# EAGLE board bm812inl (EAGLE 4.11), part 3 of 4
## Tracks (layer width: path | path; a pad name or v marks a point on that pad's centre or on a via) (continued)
N$1 (continued)
  Top 0.254: B15.B1 80.68,202.55 80.68,197.47 B15.D1 80.68,196.2 79.73,195.25 79.73,185.73 80.68,184.77 B15.J1 | B15.H1 83.86,186.68 83.86,181.6 B15.K1 83.86,180.33 82.9,179.37 82.9,171.76 | B15.V1 80.68,153.02 79.73,153.98 79.73,163.5 80.68,164.45 B15.R1 80.68,165.72 80.68,170.8 B15.N1 81.63,171.76 82.9,171.76 | 82.9,171.76 83.54,171.12 83.54,169.21 83.86,168.9 B15.P1
  Bottom 0.254: B15.C1 83.54,200.33 81.32,202.55 B15.B1 | B15.J1 81.63,184.46 85.13,184.46 85.76,185.09 85.76,186.68 84.49,186.68 B15.H1
N$2
  Top 0.254: B15.U2 77.51,156.2 77.51,161.28 B15.S2 | 76.55,188.27 77.19,187.63 B15.H2 | 76.55,188.27 74.97,189.85 B15.F2 75.28,190.8 77.51,193.03 B15.E2 | 76.55,188.27 76.55,180.01 74.97,178.42 B15.L2 74.97,177.15 77.19,174.93 B15.M2 77.19,174.3 74.97,172.07 B15.N2 74.65,166.99 73.38,165.72 73.38,160.33 74.33,159.37 B15.T2
  Bottom 0.254: B15.U2 78.46,155.24 83.54,155.24 B15.U1 | B15.T2 75.28,159.05 77.51,161.28 B15.S2
N$4
  Top 0.254: C15.B1 81.32,139.05 83.54,136.83 C15.C1 83.86,135.88 81.63,133.65 C15.D1 81.32,132.7 82.9,131.11 82.9,122.22 | 82.9,122.22 81.63,120.96 C15.J1 81.32,120 83.54,117.78 C15.K1 83.86,116.83 82.9,115.88 82.9,108.57 | 82.9,122.22 83.86,123.18 C15.H1 | C15.V1 80.68,89.52 79.73,90.47 79.73,100 80.68,100.95 C15.R1 80.68,102.22 80.68,107.3 C15.N1 81.32,108.57 82.9,108.57 | 82.9,108.57 83.54,107.94 83.54,105.72 83.86,105.4 C15.P1
N$6
  Top 0.254: C15.U2 77.19,92.38 74.97,94.6 C15.T2 75.28,95.55 77.51,97.78 C15.S2 77.51,99.05 75.92,100.63 75.92,108.89 | 75.92,108.89 77.51,110.48 C15.M2 77.19,111.43 74.97,113.65 C15.L2 74.97,114.92 75.92,115.88 75.92,123.81 | 75.92,108.89 75.28,108.25 C15.N2 | 75.92,123.81 74.97,123.81 74.97,126.35 C15.F2 | 75.92,123.81 C15.H2 77.51,124.45 77.51,129.53 C15.E2
  Bottom 0.254: C15.U1 83.54,91.74 78.46,91.74 C15.U2
N$8  (via drill 0.61)
  Top 0.254: 73.38,60.31 73.38,61.9 74.33,62.85 D15.D2 75.28,63.81 79.09,63.81 79.09,72.06 | 73.38,60.31 73.38,46.03 74.33,45.07 D15.L2 | 73.38,60.31 79.09,54.6 79.09,54.28 83.54,54.28 D15.H1 | v79.09,182.23 79.09,72.06 | 79.09,72.06 80.68,70.47 D15.B1
  Bottom 0.254: v79.09,182.23 60.36,182.23 59.41,181.28 B17.K1
N$10
  Bottom 0.254: 107.99,277.48 98.46,277.48 97.51,276.53 A14.A1 | 107.99,277.48 108.94,276.53 A13.A1 | 120.69,277.48 121.64,276.53 A12.A1 | 120.69,277.48 107.99,277.48 | 133.39,277.48 134.34,276.53 A11.A1 | 133.39,277.48 120.69,277.48 | 146.09,277.48 147.04,276.53 A10.A1 | 146.09,277.48 133.39,277.48 | 158.79,277.48 159.74,276.53 A09.A1 | 158.79,277.48 146.09,277.48 | 158.79,277.48 171.49,277.48 172.44,276.53 A08.A1 173.71,275.9 174.66,274.94 184.19,274.94 | 184.19,274.94 185.14,275.9 A07.A1 | 196.89,274.94 197.84,275.9 A06.A1 | 196.89,274.94 184.19,274.94 | 209.59,274.94 210.54,275.9 A05.A1 | 209.59,274.94 196.89,274.94 | 222.29,274.94 223.24,275.9 A04.A1 | 222.29,274.94 209.59,274.94 | 234.99,274.94 235.94,275.9 A03.A1 | 234.99,274.94 222.29,274.94 | 247.69,274.94 248.64,275.9 A02.A1 | 234.99,274.94 247.69,274.94 | 247.69,274.94 260.39,274.94 261.34,275.9 A01.A1
N$12  (via drill 0.61)
  Top 0.254: v17.82,186.68 16.23,185.09 v16.23,181.28 | v25.44,169.85 v25.44,178.11 | v12.1,169.53 9.24,166.68 9.24,153.34 8.61,152.71 8.61,150.8 v8.93,150.48 | v72.11,33.01 74.33,33.01 74.33,32.37 D15.R2
  Bottom 0.254: v17.82,186.68 19.72,186.68 20.04,186.99 B20.H1 | v16.23,181.28 17.18,180.33 19.4,180.33 20.67,179.06 24.48,179.06 v25.44,178.11 | v25.44,169.85 25.12,169.53 22.26,169.53 21.63,170.17 12.74,170.17 v12.1,169.53 | v8.93,150.48 8.93,149.85 3.21,144.13 3.21,55.23 16.23,55.23 38.45,33.01 v72.11,33.01
N$14  (via drill 0.61)
  Top 0.254: v29.88,207.31 30.83,208.27 30.83,220.97 31.47,221.6 31.47,223.51 v30.52,224.46 | v112.11,227 111.48,226.36 111.48,200.33 114.02,197.79 114.02,193.03 115.29,191.76 115.29,189.85 114.65,189.22 114.65,150.48 v114.97,150.17 | v87.67,147.31 86.08,145.72 86.08,88.25 86.4,87.94 86.4,70.79 86.08,70.47 86.08,60.95 v86.4,60.63
  Bottom 0.254: v29.88,207.31 27.66,205.09 22.26,205.09 21.31,206.05 B20.A1 | v30.52,224.46 33.37,227.32 111.8,227.32 v112.11,227 | v114.97,150.17 112.11,147.31 v87.67,147.31 | v86.4,60.63 83.22,57.46 81.63,57.46 D15.F1
N$15  (via drill 0.61)
  Top 0.254: v84.49,39.04 82.9,40.63 82.9,41.58 81.95,41.58 76.55,46.98 76.55,48.57 74.97,50.15 D15.J2 | v128.31,39.04 162.28,73.01 162.28,258.43 137.83,282.88 2.58,282.88 v2.58,237.8
  Bottom 0.254: v84.49,39.04 84.81,39.36 127.99,39.36 v128.31,39.04 | v2.58,237.8 2.58,204.46 13.69,204.46 14.64,203.51 16.86,203.51 B20.B1
N$16  (via drill 0.61)
  Top 0.254: D15.S2 78.14,29.2 79.73,30.78 79.73,36.5 80.68,37.45 D15.N1 80.36,38.4 75.92,38.4 75.92,41.26 72.74,44.44 72.74,76.19 | D16.D2 62.58,63.81 65.76,63.81 65.76,65.39 67.98,67.61 67.98,69.2 D16.B1 68.62,70.47 68.62,72.06 72.74,76.19 | v52.74,147.31 50.84,149.21 50.84,174.93 51.79,175.88 51.79,180.01 52.11,180.33 B17.K2 | v71.16,146.04 72.74,144.45 72.74,82.22 73.06,81.9 73.06,76.5 72.74,76.19
  Bottom 0.254: v52.74,147.31 54.01,146.04 v71.16,146.04
N$17  (via drill 0.61)
  Top 0.254: v74.33,53.01 82.27,45.07 82.27,43.49 83.86,41.9 D15.M1 | v25.75,71.74 v25.75,115.24 | v25.75,122.54 25.75,152.39 v27.02,153.66 | v22.9,155.88 22.58,156.2 22.58,161.28 23.21,161.91 23.21,163.82 22.58,164.45 22.58,186.68 v22.9,186.99
  Bottom 0.254: v74.33,53.01 74.01,52.69 46.71,52.69 43.53,49.52 29.56,49.52 25.75,53.33 v25.75,71.74 | v25.75,115.24 v25.75,122.54 | v27.02,153.66 24.8,155.88 v22.9,155.88 | v22.9,186.99 19.72,190.17 18.13,190.17 B20.F1
N$20  (via drill 0.61)
  Top 0.254: 28.93,179.06 28.93,182.55 29.88,183.5 B19.J1 30.52,184.77 30.52,187.63 v32.42,189.54 32.1,189.85 32.1,198.43 33.06,199.38 B19.C1 | 28.93,179.06 28.93,176.83 27.34,175.25 B19.M2 | v20.99,164.14 19.4,162.55 19.4,154.29 22.58,154.29 23.85,155.56 B19.T2 | v37.5,122.54 37.82,122.86 37.82,160.33 33.69,164.45 33.69,167.63 B19.P1 33.06,168.9 32.1,169.85 32.1,179.06 28.93,179.06
  Bottom 0.254: v32.42,189.54 32.1,189.22 25.44,189.22 24.48,190.17 B19.F2 | v20.99,164.14 21.31,163.82 27.02,163.82 31.15,167.95 32.74,167.95 B19.P1 | v37.5,122.54 38.14,121.91 60.36,121.91 61.31,120.96 C16.J2
N$21
  Top 0.254: 67.03,26.66 67.03,30.15 67.98,31.1 D16.R1 68.62,32.37 70.2,33.96 70.2,35.55 74.33,39.68 | 67.03,26.66 67.03,24.44 65.44,22.85 D16.U2 | 79.73,26.66 79.73,30.15 80.68,31.1 D15.R1 | 79.73,26.66 79.73,24.44 78.14,22.85 D15.U2 | 67.03,26.66 79.73,26.66 | 74.33,39.68 74.33,38.72 D15.N2 | 74.33,39.68 74.33,40.31 72.11,42.53 72.11,46.66 71.79,46.98 D16.K1 | C16.V2 61.63,88.25 61,87.62 61,70.79 60.68,70.47 60.68,58.72 61.63,57.77 D16.F2 | D15.K1 83.54,47.93 80.05,47.93 80.05,49.83 74.97,54.92 74.97,56.5 D15.F2
  Bottom 0.254: D16.N2 62.58,37.77 63.54,36.82 73.06,36.82 74.01,37.77 D15.N2 | D15.K1 83.54,47.93 82.59,48.88 73.06,48.88 72.11,47.93 D16.K1 | 66.08,61.58 62.27,61.58 62.27,57.77 D16.F2 | 66.08,61.58 67.66,63.17 D16.D1 | 74.33,61.58 74.33,57.77 D15.F2 | 74.33,61.58 66.08,61.58 | 74.33,61.58 78.78,61.58 80.36,63.17 D15.D1
N$22  (via drill 0.61)
  Top 0.254: 12.42,160.33 13.05,160.96 13.05,173.02 14.01,173.98 B20.M2 14.01,175.25 14.01,176.83 13.69,177.15 | 12.42,160.33 11.47,159.37 B20.T2 | 13.69,177.15 9.88,180.96 9.88,184.77 11.15,186.04 B20.F2 | v64.81,145.08 66.39,143.5 66.39,106.35 65.44,105.4 C16.P2 | v12.74,145.4 12.42,145.72 12.42,160.33 | 13.69,177.15 17.18,180.64 17.18,183.5 B20.J1 18.13,183.82 18.77,183.18 | 18.77,183.18 19.4,182.55 19.4,169.85 20.36,168.9 B20.P1 | 18.77,183.18 18.77,197.79 20.36,199.38 B20.C1
  Bottom 0.254: v64.81,145.08 64.49,145.4 v12.74,145.4
N$24
  Bottom 0.254: D15.V1 80.36,19.35 79.41,20.31 32.74,20.31 1.62,51.42 1.62,168.58 12.74,168.58 13.69,169.53 21.63,169.53 22.26,168.9 25.75,168.9 26.39,169.53 26.39,170.8 25.12,170.8 24.48,170.17 22.26,170.17 21.31,171.12 18.13,171.12 B20.N1
N$25  (via drill 0.61)
  Top 0.254: v130.85,209.54 130.85,206.68 133.07,204.46 133.07,69.2 89.25,25.39 89.25,20.94 64.49,20.94 60.68,24.75 60.68,49.2 61.63,50.15 D16.J2 | v101.64,223.19 v104.49,220.33 | v48.3,218.11 v54.33,224.14 | v20.99,209.86 15.59,204.46 15.59,195.25 14.64,194.3 B20.E2
  Bottom 0.254: v130.85,209.54 120.05,220.33 v104.49,220.33 | v101.64,223.19 101.32,223.51 95.29,223.51 94.65,224.14 v54.33,224.14 | v48.3,218.11 42.26,212.08 23.21,212.08 v20.99,209.86
N$26  (via drill 0.61)
  Top 0.254: v149.9,65.39 161.64,77.14 161.64,257.8 v139.74,279.7
  Bottom 0.254: v149.9,65.39 87.35,65.39 86.4,64.44 83.22,64.44 82.9,64.76 74.01,64.76 73.7,64.44 70.52,64.44 70.2,64.76 67.66,64.76 65.12,62.22 60.68,62.22 60.68,56.5 61.31,55.87 62.58,55.87 63.85,57.14 D16.F1 | v139.74,279.7 28.61,279.7 1.62,252.72 1.62,197.47 10.83,197.47 B20.D2
N$27  (via drill 0.61)
  Top 0.254: v96.87,24.12 139.42,66.66 139.42,274.62 133.7,280.34 133.7,281.61 133.07,282.24 13.05,282.24 13.05,270.5 4.48,261.93 4.48,237.8 3.53,236.84 3.53,236.21 3.85,235.89 3.85,218.11 3.21,217.48 3.21,210.17 4.16,209.22 4.16,197.47 2.26,195.57 v2.26,176.83 | v20.36,176.83 20.36,175.25 B20.M1
  Bottom 0.254: v96.87,24.12 86.4,24.12 84.81,22.53 D15.U1 | v2.26,176.83 2.58,176.52 20.04,176.52 v20.36,176.83
N$28
  Bottom 0.254: 104.81,274.31 99.41,274.31 99.1,273.99 94.97,273.99 94.33,273.36 A14.B1 | 104.81,274.31 105.76,273.36 A13.B1 | 117.51,274.31 118.46,273.36 A12.B1 | 117.51,274.31 104.81,274.31 | 117.51,274.31 130.21,274.31 131.16,273.36 A11.B1 132.43,273.36 135.29,273.36 136.24,274.31 142.91,274.31 143.86,273.36 A10.B1 145.13,273.36 147.99,273.36 148.94,274.31 155.61,274.31 156.56,273.36 A09.B1 157.83,273.36 158.47,273.99 162.6,273.99 162.91,274.31 171.49,274.31 | 171.49,274.31 170.53,273.36 A08.B1 | 181.01,274.31 171.49,274.31 | 181.01,274.31 181.96,273.36 A07.B1 | 193.71,274.31 194.66,273.36 A06.B1 | 193.71,274.31 181.01,274.31 | 206.41,274.31 207.36,273.36 A05.B1 | 206.41,274.31 193.71,274.31 | 219.11,274.31 220.06,273.36 A04.B1 | 219.11,274.31 206.41,274.31 | 231.81,274.31 232.76,273.36 A03.B1 | 231.81,274.31 219.11,274.31 | 244.51,274.31 245.46,273.36 A02.B1 | 244.51,274.31 231.81,274.31 | 244.51,274.31 257.21,274.31 258.16,273.36 A01.B1
N$29  (via drill 0.61)
  Top 0.254: v41.63,17.77 12.74,46.66 v12.74,101.91 | v13.37,149.53 13.05,149.85 13.05,160.33 14.01,161.28 B20.S2
  Bottom 0.254: v41.63,17.77 66.71,17.77 67.66,18.72 D16.V1 | v12.74,101.91 12.74,129.21 9.24,132.7 9.24,149.53 v13.37,149.53
N$30  (via drill 0.61)
  Top 0.254: v9.56,152.39 9.88,152.71 9.88,163.5 10.83,164.45 B20.R2
  Bottom 0.254: v9.56,152.39 5.75,148.58 2.58,148.58 2.58,51.1 32.74,20.94 69.89,20.94 70.84,21.89 D16.U1
N$34
  Top 0.254: C19.M2 27.66,111.43 32.1,111.43 32.1,122.22 33.06,123.18 C19.H1
N$35
  Bottom 0.254: C20.H2 14.01,124.45 14.01,128.89 13.69,128.89 9.88,132.7 9.88,146.36 47.66,146.36 47.98,146.04 49.25,146.04 53.06,149.85 60.36,149.85 61.63,151.12 66.71,151.12 67.66,152.07 B16.V1
N$41  (via drill 0.61)
  Top 0.254: 67.03,36.5 67.03,30.78 65.44,29.2 D16.S2 | 67.03,36.5 67.98,37.45 D16.N1 | 67.03,44.12 62.58,44.12 D16.L2 | 67.03,44.12 67.03,36.5 | 70.2,53.64 67.03,53.64 67.03,44.12 | 70.2,53.64 70.84,53.64 D16.H1 | v8.29,160.01 7.97,159.69 7.97,154.61 7.34,153.98 7.34,76.19 7.97,75.55 v7.97,74.6 | v70.52,68.25 70.2,67.93 70.2,53.64
  Bottom 0.254: v8.29,160.01 28.29,160.01 34.01,165.72 35.28,165.72 42.26,172.71 54.01,172.71 54.96,171.76 B17.N1 | v7.97,74.6 8.29,74.92 35.91,74.92 42.58,68.25 v70.52,68.25
N$46  (via drill 0.61)
  Top 0.254: v49.57,112.7 49.57,108.57 C17.N2 | v52.74,115.88 53.69,116.83 53.69,124.45 51.15,126.99 51.15,148.26 47.98,151.43 47.98,184.77 v49.57,186.36
  Bottom 0.254: v49.57,112.7 v52.74,115.88 | v49.57,186.36 49.88,186.04 63.54,186.04 64.49,186.99 B16.H2
N$49
  Bottom 0.254: 98.46,255.26 88.94,255.26 87.98,254.3 A14.J2 | 98.46,255.26 99.41,254.3 A13.J2 | 111.16,255.26 112.11,254.3 A12.J2 | 98.46,255.26 111.16,255.26 | 123.86,255.26 124.81,254.3 A11.J2 | 111.16,255.26 123.86,255.26 | 136.56,255.26 137.51,254.3 A10.J2 | 123.86,255.26 136.56,255.26 | 149.26,255.26 150.21,254.3 A09.J2 | 136.56,255.26 149.26,255.26 | 161.96,255.26 162.91,254.3 A08.J2 | 149.26,255.26 161.96,255.26 | 174.66,255.26 175.61,254.3 A07.J2 | 161.96,255.26 174.66,255.26 | 187.36,255.26 188.31,254.3 A06.J2 | 174.66,255.26 187.36,255.26 | 200.06,255.26 201.01,254.3 A05.J2 | 187.36,255.26 200.06,255.26 | 212.76,255.26 213.71,254.3 A04.J2 | 200.06,255.26 212.76,255.26 | 225.46,255.26 226.41,254.3 A03.J2 | 212.76,255.26 225.46,255.26 | 238.16,255.26 239.11,254.3 A02.J2 | 225.46,255.26 238.16,255.26 | 238.16,255.26 250.86,255.26 251.81,254.3 A01.J2
N$62
  Bottom 0.254: 104.81,233.67 95.29,233.67 94.33,234.62 A14.R1 | 104.81,233.67 105.76,234.62 A13.R1 | 117.51,233.67 118.46,234.62 A12.R1 | 104.81,233.67 117.51,233.67 | 130.21,233.67 131.16,234.62 A11.R1 | 117.51,233.67 130.21,233.67 | 142.91,233.67 143.86,234.62 A10.R1 | 130.21,233.67 142.91,233.67 | 155.61,233.67 156.56,234.62 A09.R1 | 142.91,233.67 155.61,233.67 | 168.31,233.67 169.26,234.62 A08.R1 | 155.61,233.67 168.31,233.67 | 181.01,233.67 181.96,234.62 A07.R1 | 168.31,233.67 181.01,233.67 | 193.71,233.67 194.66,234.62 A06.R1 | 181.01,233.67 193.71,233.67 | 206.41,233.67 207.36,234.62 A05.R1 | 193.71,233.67 206.41,233.67 | 219.11,233.67 220.06,234.62 A04.R1 | 206.41,233.67 219.11,233.67 | 231.81,233.67 232.76,234.62 A03.R1 | 219.11,233.67 231.81,233.67 | 244.51,233.67 245.46,234.62 A02.R1 | 231.81,233.67 244.51,233.67 | 244.51,233.67 257.21,233.67 258.16,234.62 A01.R1
N$64
  Bottom 0.254: 107.99,230.49 98.46,230.49 97.51,231.45 A14.S1 | 107.99,230.49 108.94,231.45 A13.S1 | 120.69,230.49 121.64,231.45 A12.S1 | 107.99,230.49 120.69,230.49 | 133.39,230.49 134.34,231.45 A11.S1 | 120.69,230.49 133.39,230.49 | 146.09,230.49 147.04,231.45 A10.S1 | 133.39,230.49 146.09,230.49 | 158.79,230.49 159.74,231.45 A09.S1 | 146.09,230.49 158.79,230.49 | 171.49,230.49 172.44,231.45 A08.S1 | 158.79,230.49 171.49,230.49 | 184.19,230.49 185.14,231.45 A07.S1 | 171.49,230.49 184.19,230.49 | 196.89,230.49 197.84,231.45 A06.S1 | 184.19,230.49 196.89,230.49 | 209.59,230.49 210.54,231.45 A05.S1 | 196.89,230.49 209.59,230.49 | 222.29,230.49 223.24,231.45 A04.S1 | 209.59,230.49 222.29,230.49 | 234.99,230.49 235.94,231.45 A03.S1 | 222.29,230.49 234.99,230.49 | 247.69,230.49 248.64,231.45 A02.S1 | 234.99,230.49 247.69,230.49 | 247.69,230.49 260.39,230.49 261.34,231.45 A01.S1
N$67  (via drill 0.61)
  Top 0.254: v6.07,52.69 5.75,53.01 5.75,73.97 3.53,76.19 3.53,171.44 2.26,172.71 v2.26,175.56
  Bottom 0.254: v6.07,52.69 28.29,30.47 56.23,30.47 56.55,30.78 60.68,30.78 61.31,31.42 D16.R2 | v2.26,175.56 1.31,176.52 1.31,177.79 B20.L2
N$68  (via drill 0.61)
  Top 0.254: v94.02,42.85 101.95,50.79 101.95,63.49 107.99,69.52 107.99,167.31 107.67,167.63 107.67,187.31 v109.89,189.54 | v115.92,189.22 115.92,191.76 114.65,193.03 114.65,204.14 112.43,206.36 112.43,220.02 114.02,221.6 114.02,231.13 111.48,233.67 111.48,260.34 v110.53,261.29 | v17.18,204.77 16.23,203.82 16.23,185.73 14.64,184.14 14.64,181.6 B20.K2
  Bottom 0.254: v94.02,42.85 93.7,42.53 73.06,42.53 72.11,41.58 D16.M1 | v109.89,189.54 110.21,189.22 v115.92,189.22 | v110.53,261.29 110.21,261.61 84.49,261.61 81.32,258.43 74.65,258.43 61.95,245.73 12.42,245.73 3.21,236.52 3.21,206.36 12.42,206.36 14.01,204.77 v17.18,204.77
N$70
  Bottom 0.254: 107.99,224.14 98.46,224.14 97.51,225.09 A14.U1 | 107.99,224.14 108.94,225.09 A13.U1 | 120.69,224.14 121.64,225.09 A12.U1 | 107.99,224.14 120.69,224.14 | 133.39,224.14 134.34,225.09 A11.U1 | 120.69,224.14 133.39,224.14 | 146.09,224.14 147.04,225.09 A10.U1 | 133.39,224.14 146.09,224.14 | 158.79,224.14 159.74,225.09 A09.U1 | 146.09,224.14 158.79,224.14 | 171.49,224.14 172.44,225.09 A08.U1 | 158.79,224.14 171.49,224.14 | 184.19,224.14 185.14,225.09 A07.U1 | 171.49,224.14 184.19,224.14 | 196.89,224.14 197.84,225.09 A06.U1 | 184.19,224.14 196.89,224.14 | 209.59,224.14 210.54,225.09 A05.U1 | 196.89,224.14 209.59,224.14 | 222.29,224.14 223.24,225.09 A04.U1 | 209.59,224.14 222.29,224.14 | 234.99,224.14 235.94,225.09 A03.U1 | 222.29,224.14 234.99,224.14 | 247.69,224.14 248.64,225.09 A02.U1 | 234.99,224.14 247.69,224.14 | 247.69,224.14 260.39,224.14 261.34,225.09 A01.U1
N$72
  Bottom 0.254: A14.V1 94.33,221.92 95.29,220.97 103.86,220.97 104.81,221.92 105.76,221.92 A13.V1 107.03,221.92 107.99,220.97 117.51,220.97 | 117.51,220.97 118.46,221.92 A12.V1 | 130.21,220.97 131.16,221.92 A11.V1 | 117.51,220.97 130.21,220.97 | 142.91,220.97 143.86,221.92 A10.V1 | 130.21,220.97 142.91,220.97 | 155.61,220.97 156.56,221.92 A09.V1 | 142.91,220.97 155.61,220.97 | 168.31,220.97 169.26,221.92 A08.V1 | 155.61,220.97 168.31,220.97 | 181.01,220.97 181.96,221.92 A07.V1 | 168.31,220.97 181.01,220.97 | 193.71,220.97 194.66,221.92 A06.V1 | 181.01,220.97 193.71,220.97 | 206.41,220.97 207.36,221.92 A05.V1 | 193.71,220.97 206.41,220.97 | 219.11,220.97 220.06,221.92 A04.V1 | 206.41,220.97 219.11,220.97 | 231.81,220.97 232.76,221.92 A03.V1 | 219.11,220.97 231.81,220.97 | 244.51,220.97 245.46,221.92 A02.V1 | 231.81,220.97 244.51,220.97 | 244.51,220.97 257.21,220.97 258.16,221.92 A01.V1
N$73  (via drill 0.61)
  Top 0.254: v4.16,73.65 1.62,76.19 1.62,151.12 v2.58,152.07 | v34.64,164.77 35.28,165.4 35.28,184.77 v36.87,186.36 | v49.57,187.63 47.98,189.22 47.98,191.12 v49.25,192.39 | B17.C1 v58.77,195.25
  Bottom 0.254: v4.16,73.65 8.29,73.65 8.93,74.28 31.79,74.28 32.74,73.33 D19.A1 | v2.58,152.07 7.97,157.47 26.39,157.47 33.69,164.77 v34.64,164.77 | v36.87,186.36 37.18,186.04 46.71,186.04 48.3,187.63 v49.57,187.63 | v49.25,192.39 55.6,192.39 58.46,195.25 v58.77,195.25
N$74
  Bottom 0.254: A14.V2 87.98,222.55 88.94,223.51 94.65,223.51 95.6,222.55 99.41,222.55 A13.V2 104.49,222.24 105.76,223.51 114.34,223.51 | 114.34,223.51 113.38,222.55 A12.V2 | 114.34,223.51 123.86,223.51 | 123.86,223.51 124.81,222.55 A11.V2 | 136.56,223.51 137.51,222.55 A10.V2 | 123.86,223.51 136.56,223.51 | 149.26,223.51 150.21,222.55 A09.V2 | 136.56,223.51 149.26,223.51 | 161.96,223.51 162.91,222.55 A08.V2 | 149.26,223.51 161.96,223.51 | 174.66,223.51 175.61,222.55 A07.V2 | 161.96,223.51 174.66,223.51 | 187.36,223.51 188.31,222.55 A06.V2 | 174.66,223.51 187.36,223.51 | 200.06,223.51 201.01,222.55 A05.V2 | 187.36,223.51 200.06,223.51 | 212.76,223.51 213.71,222.55 A04.V2 | 200.06,223.51 212.76,223.51 | 225.46,223.51 226.41,222.55 A03.V2 | 212.76,223.51 225.46,223.51 | 238.16,223.51 239.11,222.55 A02.V2 | 225.46,223.51 238.16,223.51 | 238.16,223.51 250.86,223.51 251.81,222.55 A01.V2
N$75
  Bottom 0.254: 107.99,207.63 102.59,207.63 102.27,207.31 98.14,207.31 97.51,206.68 B14.A1 | 107.99,207.63 108.94,206.68 B13.A1 | 120.69,207.63 121.64,206.68 B12.A1 | 107.99,207.63 120.69,207.63 | 133.39,207.63 134.34,206.68 B11.A1 | 120.69,207.63 133.39,207.63 | 146.09,207.63 147.04,206.68 B10.A1 | 133.39,207.63 146.09,207.63 | 158.79,207.63 159.74,206.68 B09.A1 | 146.09,207.63 158.79,207.63 | 158.79,207.63 171.49,207.63 172.44,206.68 B08.A1 173.71,206.05 174.66,205.09 184.19,205.09 | 184.19,205.09 185.14,206.05 B07.A1 | 196.89,205.09 197.84,206.05 B06.A1 | 184.19,205.09 196.89,205.09 | 196.89,205.09 209.59,205.09 210.54,206.05 B05.A1 211.81,206.68 212.76,207.63 222.29,207.63 | 222.29,207.63 223.24,206.68 B04.A1 | 234.99,207.63 235.94,206.68 B03.A1 | 222.29,207.63 234.99,207.63 | 247.69,207.63 248.64,206.68 B02.A1 | 234.99,207.63 247.69,207.63 | 247.69,207.63 260.39,207.63 261.34,206.68 B01.A1
N$77
  Bottom 0.254: B14.B1 94.33,203.51 95.29,204.46 104.81,204.46 105.76,203.51 B13.B1 107.03,203.51 107.99,204.46 113.38,204.46 114.34,203.51 118.46,203.51 B12.B1 119.73,203.51 120.69,204.46 130.21,204.46 131.16,203.51 B11.B1 132.43,203.51 133.39,203.51 134.34,204.46 142.91,204.46 143.86,203.51 B10.B1 145.13,203.51 147.99,203.51 148.94,204.46 155.61,204.46 156.56,203.51 B09.B1 157.83,203.51 158.47,204.14 162.6,204.14 162.91,204.46 171.49,204.46 | 244.51,204.46 234.99,204.46 234.03,203.51 B03.B1 232.76,203.51 231.81,204.46 225.14,204.46 224.19,203.51 221.33,203.51 B04.B1 220.06,203.51 219.11,204.46 206.41,204.46 | 244.51,204.46 245.46,203.51 B02.B1 | 244.51,204.46 257.21,204.46 258.16,203.51 B01.B1 | 171.49,204.46 170.53,203.51 B08.B1 | 171.49,204.46 181.01,204.46 | 181.01,204.46 181.96,203.51 B07.B1 | 193.71,204.46 194.66,203.51 B06.B1 | 181.01,204.46 193.71,204.46 | 206.41,204.46 207.36,203.51 B05.B1 | 193.71,204.46 206.41,204.46
N$82
  Bottom 0.254: 98.46,198.11 88.94,198.11 87.98,197.15 B14.D2 | 98.46,198.11 99.41,197.15 B13.D2 | 98.46,198.11 111.16,198.11 112.11,197.15 B12.D2 113.38,197.15 114.34,198.11 123.86,198.11 | 123.86,198.11 124.81,197.15 B11.D2 | 136.56,198.11 137.51,197.15 B10.D2 | 123.86,198.11 136.56,198.11 | 149.26,198.11 150.21,197.15 B09.D2 | 136.56,198.11 149.26,198.11 | 161.96,198.11 162.91,197.15 B08.D2 | 149.26,198.11 161.96,198.11 | 174.66,198.11 175.61,197.15 B07.D2 | 161.96,198.11 174.66,198.11 | 187.36,198.11 188.31,197.15 B06.D2 | 174.66,198.11 187.36,198.11 | 200.06,198.11 201.01,197.15 B05.D2 | 187.36,198.11 200.06,198.11 | 212.76,198.11 213.71,197.15 B04.D2 | 200.06,198.11 212.76,198.11 | 225.46,198.11 226.41,197.15 B03.D2 | 212.76,198.11 225.46,198.11 | 238.16,198.11 239.11,197.15 B02.D2 | 225.46,198.11 238.16,198.11 | 238.16,198.11 250.86,198.11 251.81,197.15 B01.D2
N$85
  Bottom 0.254: 101.64,194.93 92.11,194.93 91.16,193.98 B14.E2 | 101.64,194.93 102.59,193.98 B13.E2 | 114.34,194.93 115.29,193.98 B12.E2 | 101.64,194.93 114.34,194.93 | 127.04,194.93 127.99,193.98 B11.E2 | 114.34,194.93 127.04,194.93 | 139.74,194.93 140.69,193.98 B10.E2 | 127.04,194.93 139.74,194.93 | 152.44,194.93 153.39,193.98 B09.E2 | 139.74,194.93 152.44,194.93 | 165.14,194.93 166.09,193.98 B08.E2 | 152.44,194.93 165.14,194.93 | 177.84,194.93 178.79,193.98 B07.E2 | 165.14,194.93 177.84,194.93 | 190.54,194.93 191.49,193.98 B06.E2 | 177.84,194.93 190.54,194.93 | 203.24,194.93 204.19,193.98 B05.E2 | 190.54,194.93 203.24,194.93 | 215.94,194.93 216.89,193.98 B04.E2 | 203.24,194.93 215.94,194.93 | 228.64,194.93 229.59,193.98 B03.E2 | 215.94,194.93 228.64,194.93 | 241.34,194.93 242.29,193.98 B02.E2 | 228.64,194.93 241.34,194.93 | 241.34,194.93 254.04,194.93 254.99,193.98 B01.E2
N$89
  Bottom 0.254: 101.64,188.58 96.24,188.58 95.92,188.27 91.79,188.27 91.16,187.63 B14.H2 | 101.64,188.58 102.59,187.63 B13.H2 | 101.64,188.58 114.34,188.58 115.29,187.63 B12.H2 116.56,187.63 117.51,188.58 127.04,188.58 | 127.04,188.58 127.99,187.63 B11.H2 | 139.74,188.58 140.69,187.63 B10.H2 | 127.04,188.58 139.74,188.58 | 152.44,188.58 153.39,187.63 B09.H2 | 139.74,188.58 152.44,188.58 | 165.14,188.58 166.09,187.63 B08.H2 | 152.44,188.58 165.14,188.58 | 177.84,188.58 178.79,187.63 B07.H2 | 165.14,188.58 177.84,188.58 | 190.54,188.58 191.49,187.63 B06.H2 | 177.84,188.58 190.54,188.58 | 203.24,188.58 204.19,187.63 B05.H2 | 190.54,188.58 203.24,188.58 | 215.94,188.58 216.89,187.63 B04.H2 | 203.24,188.58 215.94,188.58 | 228.64,188.58 229.59,187.63 B03.H2 | 215.94,188.58 228.64,188.58 | 241.34,188.58 242.29,187.63 B02.H2 | 228.64,188.58 241.34,188.58 | 241.34,188.58 254.04,188.58 254.99,187.63 B01.H2
N$91
  Top 0.254: C20.K2 14.64,118.1 16.23,119.69 16.23,122.54 20.36,126.67 20.36,129.53 C20.E1
N$92  (via drill 0.61)
  Top 0.254: v53.69,99.68 53.69,93.65 52.74,92.7 C17.U2 | v68.93,112.38 69.57,113.02 69.57,134.29 70.2,134.93 70.2,150.48 76.24,156.52 v76.24,171.76
  Bottom 0.254: v53.69,99.68 54.33,100.32 56.87,100.32 v68.93,112.38 | v76.24,171.76 74.65,173.34 69.57,173.34 68.62,174.3 65.76,174.3 B16.M2
N$93
  Top 0.254: C20.N2 11.78,108.25 16.23,108.25 16.23,117.46 20.36,121.59 20.36,123.18 C20.H1
N$94  (via drill 0.61)
  Top 0.254: v68.3,169.53 69.57,168.26 69.57,157.79 71.16,156.2 B16.U1
  Bottom 0.254: v68.3,169.53 45.44,169.53 42.9,166.99 38.77,166.99 37.18,165.4 B18.R2
N$96  (via drill 0.61)
  Top 0.254: v76.87,132.07 76.55,132.39 76.55,144.13 78.14,145.72 v78.14,152.07 | v130.85,157.15 130.53,157.47 130.53,195.57 129.89,196.2 129.89,247.32 99.73,277.48 79.73,277.48 79.73,268.28 80.68,267.32 A15.D1
  Bottom 0.254: v76.87,132.07 70.2,132.07 70.2,126.99 68.93,125.72 48.61,125.72 48.3,126.03 47.66,126.03 47.34,125.72 42.26,125.72 39.72,128.26 28.93,128.26 28.93,120 29.56,119.37 47.66,119.37 48.61,120.32 C17.J2 | v78.14,152.07 80.36,154.29 87.35,154.29 90.52,157.47 130.53,157.47 v130.85,157.15
N$97
  Top 0.254: C19.L2 24.17,114.92 25.75,116.51 25.75,120.64 33.06,127.94 33.06,129.53 C19.E1
N$98
  Bottom 0.254: B14.J2 87.98,184.46 88.94,185.41 98.46,185.41 99.41,184.46 B13.J2 100.68,184.46 101.64,185.41 111.16,185.41 | 111.16,185.41 112.11,184.46 B12.J2 | 123.86,185.41 124.81,184.46 B11.J2 | 111.16,185.41 123.86,185.41 | 136.56,185.41 137.51,184.46 B10.J2 | 123.86,185.41 136.56,185.41 | 149.26,185.41 150.21,184.46 B09.J2 | 136.56,185.41 149.26,185.41 | 161.96,185.41 162.91,184.46 B08.J2 | 149.26,185.41 161.96,185.41 | 174.66,185.41 175.61,184.46 B07.J2 | 161.96,185.41 174.66,185.41 | 187.36,185.41 188.31,184.46 B06.J2 | 174.66,185.41 187.36,185.41 | 200.06,185.41 201.01,184.46 B05.J2 | 187.36,185.41 200.06,185.41 | 212.76,185.41 213.71,184.46 B04.J2 | 200.06,185.41 212.76,185.41 | 225.46,185.41 226.41,184.46 B03.J2 | 212.76,185.41 225.46,185.41 | 238.16,185.41 239.11,184.46 B02.J2 | 225.46,185.41 238.16,185.41 | 238.16,185.41 250.86,185.41 251.81,184.46 B01.J2
N$99  (via drill 0.61)
  Top 0.254: v41.31,120.96 43.53,123.18 43.53,124.77 45.76,126.99 45.76,129.53 C18.E1
  Bottom 0.254: v41.31,120.96 37.18,120.96 C18.J2
N$100  (via drill 0.61)
  Top 0.254: v62.9,116.19 63.85,117.14 63.85,118.73 v65.44,120.32 | v121.64,126.03 126.72,131.11 126.72,198.43 124.18,200.96 124.18,221.6 114.02,231.76 114.02,260.97 107.03,267.96 83.22,267.96 83.22,264.47 82.9,264.15 82.9,261.93 83.54,261.29 83.54,258.43 82.9,257.8 82.9,255.58 83.86,254.62 83.86,251.45 A15.K1
  Bottom 0.254: v62.9,116.19 59.09,116.19 59.09,111.75 C17.M1 | v65.44,120.32 70.84,125.72 121.32,125.72 v121.64,126.03
N$101  (via drill 0.61)
  Top 0.254: v60.36,135.56 60.68,135.88 v60.68,147.62 | v96.56,148.58 98.78,150.8 98.78,185.09 v99.41,185.73 | v87.67,186.04 85.44,188.27 85.44,195.25 84.17,196.52 84.17,198.11 85.44,199.38 85.44,232.4 v83.54,234.3
  Bottom 0.254: v60.36,135.56 60.04,135.24 49.25,135.24 46.07,132.07 28.29,132.07 28.29,120 41.63,106.67 48.93,106.67 48.93,102.22 C17.R2 | v60.68,147.62 61.63,148.58 v96.56,148.58 | v99.41,185.73 99.1,186.04 v87.67,186.04 | v83.54,234.3 81,236.84 77.19,236.84 74.97,239.06 74.97,240.65 A15.N2
N$103
  Top 0.254: D19.B1 30.83,69.52 35.28,69.52 35.28,65.08 36.23,64.12 D18.D2
N$104  (via drill 0.61)
  Top 0.254: v74.33,91.11 78.14,87.3 v78.14,84.76 | v99.1,75.87 99.73,75.24 99.73,72.69 v104.81,67.61 | v147.36,68.57 148.94,70.16 v148.94,259.07
  Bottom 0.254: v74.33,91.11 74.01,90.79 60.36,90.79 59.41,91.74 C17.U1 | v78.14,84.76 87.03,75.87 v99.1,75.87 | v104.81,67.61 108.62,67.61 108.94,67.93 117.83,67.93 118.15,67.61 121.32,67.61 121.64,67.93 130.53,67.93 130.85,67.61 134.02,67.61 134.34,67.93 143.23,67.93 143.55,67.61 146.4,67.61 v147.36,68.57 | v148.94,259.07 82.59,259.07 81,257.48 78.46,257.48 A15.H2
N$105
  Bottom 0.254: 101.64,182.23 92.11,182.23 91.16,181.28 B14.K2 | 101.64,182.23 102.59,181.28 B13.K2 | 114.34,182.23 115.29,181.28 B12.K2 | 101.64,182.23 114.34,182.23 | 127.04,182.23 127.99,181.28 B11.K2 | 114.34,182.23 127.04,182.23 | 139.74,182.23 140.69,181.28 B10.K2 | 127.04,182.23 139.74,182.23 | 152.44,182.23 153.39,181.28 B09.K2 | 139.74,182.23 152.44,182.23 | 165.14,182.23 166.09,181.28 B08.K2 | 152.44,182.23 165.14,182.23 | 177.84,182.23 178.79,181.28 B07.K2 | 165.14,182.23 177.84,182.23 | 190.54,182.23 191.49,181.28 B06.K2 | 177.84,182.23 190.54,182.23 | 203.24,182.23 204.19,181.28 B05.K2 | 190.54,182.23 203.24,182.23 | 215.94,182.23 216.89,181.28 B04.K2 | 203.24,182.23 215.94,182.23 | 228.64,182.23 229.59,181.28 B03.K2 | 215.94,182.23 228.64,182.23 | 241.34,182.23 242.29,181.28 B02.K2 | 228.64,182.23 241.34,182.23 | 241.34,182.23 254.04,182.23 254.99,181.28 B01.K2
N$107
  Bottom 0.254: 98.46,179.06 88.94,179.06 87.98,178.11 B14.L2 | 98.46,179.06 99.41,178.11 B13.L2 | 111.16,179.06 112.11,178.11 B12.L2 | 98.46,179.06 111.16,179.06 | 123.86,179.06 124.81,178.11 B11.L2 | 111.16,179.06 123.86,179.06 | 136.56,179.06 137.51,178.11 B10.L2 | 123.86,179.06 136.56,179.06 | 149.26,179.06 150.21,178.11 B09.L2 | 136.56,179.06 149.26,179.06 | 161.96,179.06 162.91,178.11 B08.L2 | 149.26,179.06 161.96,179.06 | 174.66,179.06 175.61,178.11 B07.L2 | 161.96,179.06 174.66,179.06 | 187.36,179.06 188.31,178.11 B06.L2 | 174.66,179.06 187.36,179.06 | 200.06,179.06 201.01,178.11 B05.L2 | 187.36,179.06 200.06,179.06 | 212.76,179.06 213.71,178.11 B04.L2 | 200.06,179.06 212.76,179.06 | 225.46,179.06 226.41,178.11 B03.L2 | 212.76,179.06 225.46,179.06 | 238.16,179.06 239.11,178.11 B02.L2 | 225.46,179.06 238.16,179.06 | 238.16,179.06 250.86,179.06 251.81,178.11 B01.L2
N$108  (via drill 0.61)
  Top 0.254: v102.91,58.09 110.84,66.03 110.84,165.09 108.3,167.63 108.3,168.9 111.48,172.07 111.48,198.43 v111.8,198.74 | v55.28,198.43 54.33,197.47 54.33,192.08 55.28,191.12 B17.F1
  Bottom 0.254: v102.91,58.09 102.59,58.41 86.71,58.41 84.17,55.87 67.66,55.87 67.03,56.5 65.12,56.5 63.85,55.23 41.31,55.23 40.36,54.28 D18.H2 | v111.8,198.74 86.08,198.74 85.13,197.79 81.95,197.79 81.63,198.11 72.74,198.11 72.43,197.79 70.52,197.79 69.57,198.74 60.68,198.74 59.73,197.79 56.55,197.79 55.92,198.43 v55.28,198.43
N$109  (via drill 0.61)
  Top 0.254: v55.92,85.39 55.92,88.25 C17.V1 | v123.23,75.24 125.45,77.46 125.45,86.98 127.35,88.89 127.35,139.69 129.89,142.23 129.89,195.57 127.99,197.47 127.99,198.74 127.35,199.38 127.35,228.9 v127.67,229.22
  Bottom 0.254: v55.92,85.39 56.23,85.71 81.32,85.71 90.21,76.82 101,76.82 101.64,76.19 116.24,76.19 117.19,75.24 v123.23,75.24 | v127.67,229.22 127.04,229.86 90.52,229.86 89.89,230.49 83.54,230.49 81.32,232.71 81.32,234.3 A15.R1
N$111
  Top 0.254: D18.J2 36.87,51.42 37.82,52.38 37.82,60.31 33.69,64.44 33.69,66.03 D19.C1
N$112  (via drill 0.61)
  Top 0.254: v7.97,72.69 7.02,73.65 7.02,75.87 6.7,76.19 6.7,154.93 v7.02,155.24
  Bottom 0.254: v7.97,72.69 10.2,72.69 14.32,68.57 23.53,68.57 23.53,64.12 D19.D2 | v7.02,155.24 8.61,156.83 40.68,156.83 41.31,157.47 47.66,157.47 48.61,158.42 B17.T2
N$113  (via drill 0.61)
  Top 0.254: v21.31,77.14 19.4,75.24 19.4,44.75 23.21,44.75 D19.L2 | v15.59,133.34 13.05,135.88 13.05,143.81 16.55,147.31 16.55,151.43 16.23,151.75 16.23,161.28 v17.82,162.86 | v31.79,161.59 v30.2,163.18 | v45.12,166.36 44.8,166.68 44.8,169.53 45.12,169.85 45.12,173.66 44.49,174.3 v44.49,180.01 | v69.57,181.28 71.16,182.87 71.16,186.68 B16.H1
  Bottom 0.254: v21.31,77.14 21.31,78.09 22.26,79.05 22.26,90.79 20.04,90.79 15.59,95.24 v15.59,133.34 | v17.82,162.86 18.13,163.18 v30.2,163.18 | v31.79,161.59 31.79,162.23 33.37,163.82 38.14,163.82 40.68,166.36 v45.12,166.36 | v44.49,180.01 44.8,179.69 49.88,179.69 50.2,180.01 50.84,180.01 51.79,179.06 58.77,179.06 61.31,176.52 64.49,176.52 69.25,181.28 v69.57,181.28
N$115
  Bottom 0.254: 101.64,175.88 92.11,175.88 91.16,174.93 B14.M2 | 101.64,175.88 102.59,174.93 B13.M2 | 114.34,175.88 115.29,174.93 B12.M2 | 101.64,175.88 114.34,175.88 | 127.04,175.88 127.99,174.93 B11.M2 | 114.34,175.88 127.04,175.88 | 139.74,175.88 140.69,174.93 B10.M2 | 127.04,175.88 139.74,175.88 | 152.44,175.88 153.39,174.93 B09.M2 | 139.74,175.88 152.44,175.88 | 165.14,175.88 166.09,174.93 B08.M2 | 152.44,175.88 165.14,175.88 | 177.84,175.88 178.79,174.93 B07.M2 | 165.14,175.88 177.84,175.88 | 190.54,175.88 191.49,174.93 B06.M2 | 177.84,175.88 190.54,175.88 | 203.24,175.88 204.19,174.93 B05.M2 | 190.54,175.88 203.24,175.88 | 215.94,175.88 216.89,174.93 B04.M2 | 203.24,175.88 215.94,175.88 | 228.64,175.88 229.59,174.93 B03.M2 | 215.94,175.88 228.64,175.88 | 241.34,175.88 242.29,174.93 B02.M2 | 228.64,175.88 241.34,175.88 | 241.34,175.88 254.04,175.88 254.99,174.93 B01.M2
N$121
  Bottom 0.254: 101.64,169.53 92.11,169.53 91.16,168.58 B14.P2 | 101.64,169.53 102.59,168.58 B13.P2 | 114.34,169.53 115.29,168.58 B12.P2 | 101.64,169.53 114.34,169.53 | 127.04,169.53 127.99,168.58 B11.P2 | 114.34,169.53 127.04,169.53 | 139.74,169.53 140.69,168.58 B10.P2 | 127.04,169.53 139.74,169.53 | 152.44,169.53 153.39,168.58 B09.P2 | 139.74,169.53 152.44,169.53 | 165.14,169.53 166.09,168.58 B08.P2 | 152.44,169.53 165.14,169.53 | 177.84,169.53 178.79,168.58 B07.P2 | 165.14,169.53 177.84,169.53 | 190.54,169.53 191.49,168.58 B06.P2 | 177.84,169.53 190.54,169.53 | 203.24,169.53 204.19,168.58 B05.P2 | 190.54,169.53 203.24,169.53 | 215.94,169.53 216.89,168.58 B04.P2 | 203.24,169.53 215.94,169.53 | 228.64,169.53 229.59,168.58 B03.P2 | 215.94,169.53 228.64,169.53 | 241.34,169.53 242.29,168.58 B02.P2 | 228.64,169.53 241.34,169.53 | 241.34,169.53 254.04,169.53 254.99,168.58 B01.P2
N$122
  Top 0.254: C16.D1 67.98,133.97 67.98,139.05 C16.B1 | C16.V1 67.98,89.52 67.03,90.47 67.03,100 67.98,100.95 C16.R1 68.93,101.91 71.16,104.13 C16.P1 70.84,105.08 70.2,105.72 | 70.2,105.72 68.62,107.3 C16.N1 | 70.2,105.72 70.2,115.88 71.16,116.83 C16.K1 71.16,118.1 71.16,123.18 C16.H1 71.16,124.45 70.2,125.4 70.2,130.8 70.84,131.43 70.84,135.56 71.16,135.88 C16.C1
  Bottom 0.254: C16.C1 70.84,136.83 68.62,139.05 C16.B1 | C16.J1 68.93,120.96 71.16,123.18 C16.H1
N$123
  Bottom 0.254: 104.81,163.82 95.29,163.82 94.33,164.77 B14.R1 | 104.81,163.82 105.76,164.77 B13.R1 | 117.51,163.82 118.46,164.77 B12.R1 | 104.81,163.82 117.51,163.82 | 130.21,163.82 131.16,164.77 B11.R1 | 117.51,163.82 130.21,163.82 | 142.91,163.82 143.86,164.77 B10.R1 | 130.21,163.82 142.91,163.82 | 155.61,163.82 156.56,164.77 B09.R1 | 142.91,163.82 155.61,163.82 | 168.31,163.82 169.26,164.77 B08.R1 | 155.61,163.82 168.31,163.82 | 181.01,163.82 181.96,164.77 B07.R1 | 168.31,163.82 181.01,163.82 | 193.71,163.82 194.66,164.77 B06.R1 | 181.01,163.82 193.71,163.82 | 206.41,163.82 207.36,164.77 B05.R1 | 193.71,163.82 206.41,163.82 | 219.11,163.82 220.06,164.77 B04.R1 | 206.41,163.82 219.11,163.82 | 231.81,163.82 232.76,164.77 B03.R1 | 219.11,163.82 231.81,163.82 | 244.51,163.82 245.46,164.77 B02.R1 | 231.81,163.82 244.51,163.82 | 244.51,163.82 257.21,163.82 258.16,164.77 B01.R1
N$126
  Bottom 0.254: 98.46,166.36 88.94,166.36 87.98,165.4 B14.R2 | 98.46,166.36 99.41,165.4 B13.R2 | 111.16,166.36 112.11,165.4 B12.R2 | 98.46,166.36 111.16,166.36 | 123.86,166.36 124.81,165.4 B11.R2 | 111.16,166.36 123.86,166.36 | 136.56,166.36 137.51,165.4 B10.R2 | 123.86,166.36 136.56,166.36 | 149.26,166.36 150.21,165.4 B09.R2 | 136.56,166.36 149.26,166.36 | 161.96,166.36 162.91,165.4 B08.R2 | 149.26,166.36 161.96,166.36 | 174.66,166.36 175.61,165.4 B07.R2 | 161.96,166.36 174.66,166.36 | 187.36,166.36 188.31,165.4 B06.R2 | 174.66,166.36 187.36,166.36 | 200.06,166.36 201.01,165.4 B05.R2 | 187.36,166.36 200.06,166.36 | 212.76,166.36 213.71,165.4 B04.R2 | 200.06,166.36 212.76,166.36 | 225.46,166.36 226.41,165.4 B03.R2 | 212.76,166.36 225.46,166.36 | 238.16,166.36 239.11,165.4 B02.R2 | 225.46,166.36 238.16,166.36 | 238.16,166.36 250.86,166.36 251.81,165.4 B01.R2
N$127
  Bottom 0.254: 107.99,160.64 98.46,160.64 97.51,161.59 B14.S1 | 107.99,160.64 108.94,161.59 B13.S1 | 120.69,160.64 121.64,161.59 B12.S1 | 107.99,160.64 120.69,160.64 | 133.39,160.64 134.34,161.59 B11.S1 | 120.69,160.64 133.39,160.64 | 146.09,160.64 147.04,161.59 B10.S1 | 133.39,160.64 146.09,160.64 | 158.79,160.64 159.74,161.59 B09.S1 | 146.09,160.64 158.79,160.64 | 171.49,160.64 172.44,161.59 B08.S1 | 158.79,160.64 171.49,160.64 | 184.19,160.64 185.14,161.59 B07.S1 | 171.49,160.64 184.19,160.64 | 196.89,160.64 197.84,161.59 B06.S1 | 184.19,160.64 196.89,160.64 | 209.59,160.64 210.54,161.59 B05.S1 | 196.89,160.64 209.59,160.64 | 222.29,160.64 223.24,161.59 B04.S1 | 209.59,160.64 222.29,160.64 | 234.99,160.64 235.94,161.59 B03.S1 | 222.29,160.64 234.99,160.64 | 247.69,160.64 248.64,161.59 B02.S1 | 234.99,160.64 247.69,160.64 | 247.69,160.64 260.39,160.64 261.34,161.59 B01.S1
N$128  (via drill 0.61)
  Top 0.254: v28.29,88.89 28.29,57.46 24.48,57.46 D19.F2 | v114.97,93.97 117.83,96.83 v117.83,204.46 | v71.16,202.24 70.2,201.28 70.2,199.06 69.57,198.43 69.57,192.08 68.62,191.12 B16.F1
  Bottom 0.254: v28.29,88.89 30.2,90.79 55.6,90.79 58.14,93.33 60.68,93.33 61,93.02 64.17,93.02 64.49,93.33 73.38,93.33 73.7,93.02 76.87,93.02 77.82,93.97 v114.97,93.97 | v117.83,204.46 114.02,204.46 113.38,205.09 74.01,205.09 v71.16,202.24
N$129  (via drill 0.61)
  Top 0.254: v133.7,205.09 133.7,62.22 95.6,24.12 95.6,10.78 60.04,10.78 25.75,45.07 25.75,48.57 24.17,50.15 D19.J2 | v113.7,206.68 113.38,207 v113.38,209.86 | v106.08,209.86 104.49,209.86 104.18,209.54 v99.41,209.54 | v72.11,209.86 70.2,207.95 70.2,204.77 72.11,202.87 72.11,201.28 72.74,200.65 72.74,195.25 71.79,194.3 B16.E1
  Bottom 0.254: v133.7,205.09 119.42,205.09 118.78,205.73 117.19,205.73 116.56,205.09 115.29,205.09 v113.7,206.68 | v106.08,209.86 v113.38,209.86 | v99.41,209.54 99.1,209.86 v72.11,209.86
N$130
  Bottom 0.254: 101.64,163.18 92.11,163.18 91.16,162.23 B14.S2 | 101.64,163.18 102.59,162.23 B13.S2 | 114.34,163.18 115.29,162.23 B12.S2 | 101.64,163.18 114.34,163.18 | 127.04,163.18 127.99,162.23 B11.S2 | 114.34,163.18 127.04,163.18 | 139.74,163.18 140.69,162.23 B10.S2 | 127.04,163.18 139.74,163.18 | 152.44,163.18 153.39,162.23 B09.S2 | 139.74,163.18 152.44,163.18 | 165.14,163.18 166.09,162.23 B08.S2 | 152.44,163.18 165.14,163.18 | 177.84,163.18 178.79,162.23 B07.S2 | 165.14,163.18 177.84,163.18 | 190.54,163.18 191.49,162.23 B06.S2 | 177.84,163.18 190.54,163.18 | 203.24,163.18 204.19,162.23 B05.S2 | 190.54,163.18 203.24,163.18 | 215.94,163.18 216.89,162.23 B04.S2 | 203.24,163.18 215.94,163.18 | 228.64,163.18 229.59,162.23 B03.S2 | 215.94,163.18 228.64,163.18 | 241.34,163.18 242.29,162.23 B02.S2 | 228.64,163.18 241.34,163.18 | 241.34,163.18 254.04,163.18 254.99,162.23 B01.S2
N$132  (via drill 0.61)
  Top 0.254: v54.01,180.64 53.06,179.69 53.06,177.79 53.69,177.15 53.69,161.28 53.06,160.64 53.06,156.52 52.74,156.2 B17.U2
  Bottom 0.254: v54.01,180.64 54.96,181.6 57.5,181.6 58.77,182.87 66.71,182.87 67.66,183.82 B16.J1
N$134
  Bottom 0.254: 107.99,154.29 98.46,154.29 97.51,155.24 B14.U1 | 107.99,154.29 108.94,155.24 B13.U1 | 120.69,154.29 121.64,155.24 B12.U1 | 107.99,154.29 120.69,154.29 | 133.39,154.29 134.34,155.24 B11.U1 | 120.69,154.29 133.39,154.29 | 146.09,154.29 147.04,155.24 B10.U1 | 133.39,154.29 146.09,154.29 | 158.79,154.29 159.74,155.24 B09.U1 | 146.09,154.29 158.79,154.29 | 171.49,154.29 172.44,155.24 B08.U1 | 158.79,154.29 171.49,154.29 | 184.19,154.29 185.14,155.24 B07.U1 | 171.49,154.29 184.19,154.29 | 196.89,154.29 197.84,155.24 B06.U1 | 184.19,154.29 196.89,154.29 | 209.59,154.29 210.54,155.24 B05.U1 | 196.89,154.29 209.59,154.29 | 222.29,154.29 223.24,155.24 B04.U1 | 209.59,154.29 222.29,154.29 | 234.99,154.29 235.94,155.24 B03.U1 | 222.29,154.29 234.99,154.29 | 247.69,154.29 248.64,155.24 B02.U1 | 234.99,154.29 247.69,154.29 | 247.69,154.29 260.39,154.29 261.34,155.24 B01.U1
N$135
  Bottom 0.254: 101.64,156.83 92.11,156.83 91.16,155.88 B14.U2 | 101.64,156.83 102.59,155.88 B13.U2 | 114.34,156.83 115.29,155.88 B12.U2 | 101.64,156.83 114.34,156.83 | 114.34,156.83 127.04,156.83 127.99,155.88 B11.U2 129.26,155.88 129.58,156.2 133.7,156.2 134.34,156.83 142.91,156.83 | 142.91,156.83 141.96,155.88 B10.U2 | 142.91,156.83 152.44,156.83 | 152.44,156.83 153.39,155.88 B09.U2 | 165.14,156.83 166.09,155.88 B08.U2 | 152.44,156.83 165.14,156.83 | 177.84,156.83 178.79,155.88 B07.U2 | 165.14,156.83 177.84,156.83 | 190.54,156.83 191.49,155.88 B06.U2 | 177.84,156.83 190.54,156.83 | 203.24,156.83 204.19,155.88 B05.U2 | 190.54,156.83 203.24,156.83 | 215.94,156.83 216.89,155.88 B04.U2 | 203.24,156.83 215.94,156.83 | 228.64,156.83 229.59,155.88 B03.U2 | 215.94,156.83 228.64,156.83 | 241.34,156.83 242.29,155.88 B02.U2 | 228.64,156.83 241.34,156.83 | 241.34,156.83 254.04,156.83 254.99,155.88 B01.U2
N$136
  Bottom 0.254: 104.81,151.12 95.29,151.12 94.33,152.07 B14.V1 | 104.81,151.12 105.76,152.07 B13.V1 | 117.51,151.12 118.46,152.07 B12.V1 | 104.81,151.12 117.51,151.12 | 130.21,151.12 131.16,152.07 B11.V1 | 117.51,151.12 130.21,151.12 | 142.91,151.12 143.86,152.07 B10.V1 | 130.21,151.12 142.91,151.12 | 155.61,151.12 156.56,152.07 B09.V1 | 142.91,151.12 155.61,151.12 | 168.31,151.12 169.26,152.07 B08.V1 | 155.61,151.12 168.31,151.12 | 181.01,151.12 181.96,152.07 B07.V1 | 168.31,151.12 181.01,151.12 | 193.71,151.12 194.66,152.07 B06.V1 | 181.01,151.12 193.71,151.12 | 206.41,151.12 207.36,152.07 B05.V1 | 193.71,151.12 206.41,151.12 | 219.11,151.12 220.06,152.07 B04.V1 | 206.41,151.12 219.11,151.12 | 231.81,151.12 232.76,152.07 B03.V1 | 219.11,151.12 231.81,151.12 | 244.51,151.12 245.46,152.07 B02.V1 | 231.81,151.12 244.51,151.12 | 244.51,151.12 257.21,151.12 258.16,152.07 B01.V1
N$141
  Bottom 0.254: 107.99,141.59 98.46,141.59 97.51,142.55 C14.A1 | 107.99,141.59 108.94,142.55 C13.A1 | 107.99,141.59 120.69,141.59 121.64,142.55 C12.A1 122.91,143.18 123.86,144.13 133.39,144.13 | 133.39,144.13 134.34,143.18 C11.A1 | 146.09,144.13 147.04,143.18 C10.A1 | 133.39,144.13 146.09,144.13 | 158.79,144.13 159.74,143.18 C09.A1 | 146.09,144.13 158.79,144.13 | 158.79,144.13 171.49,144.13 172.44,143.18 C08.A1 173.71,142.55 174.66,141.59 184.19,141.59 | 184.19,141.59 185.14,142.55 C07.A1 | 196.89,141.59 197.84,142.55 C06.A1 | 184.19,141.59 196.89,141.59 | 209.59,141.59 210.54,142.55 C05.A1 | 196.89,141.59 209.59,141.59 | 222.29,141.59 223.24,142.55 C04.A1 | 209.59,141.59 222.29,141.59 | 222.29,141.59 234.99,141.59 235.94,142.55 C03.A1 237.21,143.18 238.16,144.13 247.69,144.13 | 247.69,144.13 248.64,143.18 C02.A1 | 247.69,144.13 260.39,144.13 261.34,143.18 C01.A1
N$144
  Bottom 0.254: 104.81,140.96 95.29,140.96 94.33,140.01 C14.B1 | 104.81,140.96 105.76,140.01 C13.B1 | 117.51,140.96 118.46,140.01 C12.B1 | 117.51,140.96 104.81,140.96 | 117.51,140.96 130.21,140.96 131.16,140.01 C11.B1 132.43,140.01 135.29,140.01 136.24,140.96 142.91,140.96 143.86,140.01 C10.B1 145.13,140.01 147.99,140.01 148.94,140.96 155.61,140.96 156.56,140.01 C09.B1 157.83,140.01 158.47,140.64 162.6,140.64 162.91,140.96 171.49,140.96 | 171.49,140.96 170.53,140.01 C08.B1 | 171.49,140.96 181.01,140.96 | 181.01,140.96 181.96,140.01 C07.B1 | 193.71,140.96 194.66,140.01 C06.B1 | 181.01,140.96 193.71,140.96 | 206.41,140.96 207.36,140.01 C05.B1 | 193.71,140.96 206.41,140.96 | 219.11,140.96 220.06,140.01 C04.B1 | 206.41,140.96 219.11,140.96 | 231.81,140.96 232.76,140.01 C03.B1 | 219.11,140.96 231.81,140.96 | 231.81,140.96 244.51,140.96 245.46,140.01 C02.B1 246.73,140.01 249.59,140.01 250.54,140.96 257.21,140.96 258.16,140.01 C01.B1
N$154
  Bottom 0.254: 104.81,132.07 95.29,132.07 94.33,133.02 C14.D1 | 104.81,132.07 105.76,133.02 C13.D1 | 117.51,132.07 118.46,133.02 C12.D1 | 117.51,132.07 104.81,132.07 | 130.21,132.07 131.16,133.02 C11.D1 | 130.21,132.07 117.51,132.07 | 142.91,132.07 143.86,133.02 C10.D1 | 130.21,132.07 142.91,132.07 | 155.61,132.07 156.56,133.02 C09.D1 | 142.91,132.07 155.61,132.07 | 168.31,132.07 169.26,133.02 C08.D1 | 155.61,132.07 168.31,132.07 | 181.01,132.07 181.96,133.02 C07.D1 | 168.31,132.07 181.01,132.07 | 193.71,132.07 194.66,133.02 C06.D1 | 181.01,132.07 193.71,132.07 | 206.41,132.07 207.36,133.02 C05.D1 | 193.71,132.07 206.41,132.07 | 219.11,132.07 220.06,133.02 C04.D1 | 206.41,132.07 219.11,132.07 | 231.81,132.07 232.76,133.02 C03.D1 | 219.11,132.07 231.81,132.07 | 244.51,132.07 245.46,133.02 C02.D1 | 231.81,132.07 244.51,132.07 | 244.51,132.07 257.21,132.07 258.16,133.02 C01.D1
N$156
  Bottom 0.254: 98.46,134.61 88.94,134.61 87.98,133.65 C14.D2 | 98.46,134.61 99.41,133.65 C13.D2 | 111.16,134.61 112.11,133.65 C12.D2 | 111.16,134.61 98.46,134.61 | 123.86,134.61 124.81,133.65 C11.D2 | 123.86,134.61 111.16,134.61 | 123.86,134.61 136.56,134.61 137.51,133.65 C10.D2 138.78,133.65 139.74,134.61 146.09,134.61 147.04,133.65 150.21,133.65 C09.D2 151.48,133.65 152.44,134.61 161.96,134.61 | 161.96,134.61 162.91,133.65 C08.D2 | 174.66,134.61 175.61,133.65 C07.D2 | 161.96,134.61 174.66,134.61 | 187.36,134.61 188.31,133.65 C06.D2 | 174.66,134.61 187.36,134.61 | 200.06,134.61 201.01,133.65 C05.D2 | 187.36,134.61 200.06,134.61 | 212.76,134.61 213.71,133.65 C04.D2 | 200.06,134.61 212.76,134.61 | 225.46,134.61 226.41,133.65 C03.D2 | 212.76,134.61 225.46,134.61 | 238.16,134.61 239.11,133.65 C02.D2 | 225.46,134.61 238.16,134.61 | 238.16,134.61 250.86,134.61 251.81,133.65 C01.D2
N$157
  Bottom 0.254: 107.99,128.89 102.59,128.89 101.95,129.53 97.83,129.53 97.51,129.84 C14.E1 | 107.99,128.89 108.94,129.84 C13.E1 | 120.69,128.89 121.64,129.84 C12.E1 | 120.69,128.89 107.99,128.89 | 133.39,128.89 134.34,129.84 C11.E1 | 133.39,128.89 120.69,128.89 | 146.09,128.89 147.04,129.84 C10.E1 | 133.39,128.89 146.09,128.89 | 158.79,128.89 159.74,129.84 C09.E1 | 146.09,128.89 158.79,128.89 | 171.49,128.89 172.44,129.84 C08.E1 | 158.79,128.89 171.49,128.89 | 184.19,128.89 185.14,129.84 C07.E1 | 171.49,128.89 184.19,128.89 | 196.89,128.89 197.84,129.84 C06.E1 | 184.19,128.89 196.89,128.89 | 209.59,128.89 210.54,129.84 C05.E1 | 196.89,128.89 209.59,128.89 | 222.29,128.89 223.24,129.84 C04.E1 | 209.59,128.89 222.29,128.89 | 234.99,128.89 235.94,129.84 C03.E1 | 222.29,128.89 234.99,128.89 | 247.69,128.89 248.64,129.84 C02.E1 | 234.99,128.89 247.69,128.89 | 247.69,128.89 260.39,128.89 261.34,129.84 C01.E1
N$158
  Bottom 0.254: 101.64,131.43 92.11,131.43 91.16,130.48 C14.E2 | 101.64,131.43 102.59,130.48 C13.E2 | 114.34,131.43 115.29,130.48 C12.E2 | 114.34,131.43 101.64,131.43 | 127.04,131.43 127.99,130.48 C11.E2 | 127.04,131.43 114.34,131.43 | 139.74,131.43 140.69,130.48 C10.E2 | 127.04,131.43 139.74,131.43 | 152.44,131.43 153.39,130.48 C09.E2 | 139.74,131.43 152.44,131.43 | 165.14,131.43 166.09,130.48 C08.E2 | 152.44,131.43 165.14,131.43 | 177.84,131.43 178.79,130.48 C07.E2 | 165.14,131.43 177.84,131.43 | 190.54,131.43 191.49,130.48 C06.E2 | 177.84,131.43 190.54,131.43 | 203.24,131.43 204.19,130.48 C05.E2 | 190.54,131.43 203.24,131.43 | 215.94,131.43 216.89,130.48 C04.E2 | 203.24,131.43 215.94,131.43 | 228.64,131.43 229.59,130.48 C03.E2 | 215.94,131.43 228.64,131.43 | 241.34,131.43 242.29,130.48 C02.E2 | 228.64,131.43 241.34,131.43 | 241.34,131.43 254.04,131.43 254.99,130.48 C01.E2
N$163
  Bottom 0.254: 107.99,122.54 98.46,122.54 97.51,123.49 C14.H1 | 107.99,122.54 108.94,123.49 C13.H1 | 120.69,122.54 121.64,123.49 C12.H1 | 120.69,122.54 107.99,122.54 | 133.39,122.54 134.34,123.49 C11.H1 | 133.39,122.54 120.69,122.54 | 146.09,122.54 147.04,123.49 C10.H1 | 133.39,122.54 146.09,122.54 | 158.79,122.54 159.74,123.49 C09.H1 | 146.09,122.54 158.79,122.54 | 171.49,122.54 172.44,123.49 C08.H1 | 158.79,122.54 171.49,122.54 | 184.19,122.54 185.14,123.49 C07.H1 | 171.49,122.54 184.19,122.54 | 196.89,122.54 197.84,123.49 C06.H1 | 184.19,122.54 196.89,122.54 | 209.59,122.54 210.54,123.49 C05.H1 | 196.89,122.54 209.59,122.54 | 222.29,122.54 223.24,123.49 C04.H1 | 209.59,122.54 222.29,122.54 | 234.99,122.54 235.94,123.49 C03.H1 | 222.29,122.54 234.99,122.54 | 247.69,122.54 248.64,123.49 C02.H1 | 234.99,122.54 247.69,122.54 | 247.69,122.54 260.39,122.54 261.34,123.49 C01.H1
N$164
  Bottom 0.254: 101.64,125.08 92.11,125.08 91.16,124.13 C14.H2 | 101.64,125.08 102.59,124.13 C13.H2 | 114.34,125.08 115.29,124.13 C12.H2 | 114.34,125.08 101.64,125.08 | 127.04,125.08 127.99,124.13 C11.H2 | 127.04,125.08 114.34,125.08 | 139.74,125.08 140.69,124.13 C10.H2 | 139.74,125.08 127.04,125.08 | 152.44,125.08 153.39,124.13 C09.H2 | 139.74,125.08 152.44,125.08 | 165.14,125.08 166.09,124.13 C08.H2 | 152.44,125.08 165.14,125.08 | 177.84,125.08 178.79,124.13 C07.H2 | 165.14,125.08 177.84,125.08 | 190.54,125.08 191.49,124.13 C06.H2 | 177.84,125.08 190.54,125.08 | 203.24,125.08 204.19,124.13 C05.H2 | 190.54,125.08 203.24,125.08 | 215.94,125.08 216.89,124.13 C04.H2 | 203.24,125.08 215.94,125.08 | 228.64,125.08 229.59,124.13 C03.H2 | 215.94,125.08 228.64,125.08 | 241.34,125.08 242.29,124.13 C02.H2 | 228.64,125.08 241.34,125.08 | 241.34,125.08 254.04,125.08 254.99,124.13 C01.H2
N$165
  Bottom 0.254: 104.81,119.37 95.29,119.37 94.33,120.32 C14.J1 | 104.81,119.37 105.76,120.32 C13.J1 | 117.51,119.37 118.46,120.32 C12.J1 | 117.51,119.37 104.81,119.37 | 130.21,119.37 131.16,120.32 C11.J1 | 130.21,119.37 117.51,119.37 | 142.91,119.37 143.86,120.32 C10.J1 | 142.91,119.37 130.21,119.37 | 155.61,119.37 156.56,120.32 C09.J1 | 142.91,119.37 155.61,119.37 | 168.31,119.37 169.26,120.32 C08.J1 | 155.61,119.37 168.31,119.37 | 181.01,119.37 181.96,120.32 C07.J1 | 168.31,119.37 181.01,119.37 | 193.71,119.37 194.66,120.32 C06.J1 | 181.01,119.37 193.71,119.37 | 206.41,119.37 207.36,120.32 C05.J1 | 193.71,119.37 206.41,119.37 | 219.11,119.37 220.06,120.32 C04.J1 | 206.41,119.37 219.11,119.37 | 231.81,119.37 232.76,120.32 C03.J1 | 219.11,119.37 231.81,119.37 | 244.51,119.37 245.46,120.32 C02.J1 | 231.81,119.37 244.51,119.37 | 244.51,119.37 257.21,119.37 258.16,120.32 C01.J1
N$166
  Bottom 0.254: 98.46,121.91 88.94,121.91 87.98,120.96 C14.J2 | 98.46,121.91 99.41,120.96 C13.J2 | 111.16,121.91 112.11,120.96 C12.J2 | 111.16,121.91 98.46,121.91 | 123.86,121.91 124.81,120.96 C11.J2 | 123.86,121.91 111.16,121.91 | 136.56,121.91 137.51,120.96 C10.J2 | 136.56,121.91 123.86,121.91 | 149.26,121.91 150.21,120.96 C09.J2 | 136.56,121.91 149.26,121.91 | 161.96,121.91 162.91,120.96 C08.J2 | 149.26,121.91 161.96,121.91 | 174.66,121.91 175.61,120.96 C07.J2 | 161.96,121.91 174.66,121.91 | 187.36,121.91 188.31,120.96 C06.J2 | 174.66,121.91 187.36,121.91 | 200.06,121.91 201.01,120.96 C05.J2 | 187.36,121.91 200.06,121.91 | 212.76,121.91 213.71,120.96 C04.J2 | 200.06,121.91 212.76,121.91 | 225.46,121.91 226.41,120.96 C03.J2 | 212.76,121.91 225.46,121.91 | 238.16,121.91 239.11,120.96 C02.J2 | 225.46,121.91 238.16,121.91 | 238.16,121.91 250.86,121.91 251.81,120.96 C01.J2
N$167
